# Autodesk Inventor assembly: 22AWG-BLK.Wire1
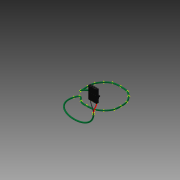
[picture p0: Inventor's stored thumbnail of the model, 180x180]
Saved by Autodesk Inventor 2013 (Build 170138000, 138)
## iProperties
Part Number: 22AWG-BLK.Wire1
Material: Default
Description: 22AWG-BLK
Stock Number: 22AWG-BLK
Density: 1 g/cm^3
Part Number: 22AWG-RED.Wire2
Description: 22AWG-RED
Stock Number: 22AWG-RED
ParentFileIdentifier: 5|1|0|0|180|2|0|0|80|0|65|0|84|0|72|0|83|0|59|0|67|0|58|0|92|0|80|0|114|0|111|0|103|0|114|0|97|0|109|0|32|0|70|0|105|0|108|0|101|0|115|0|92|0|65|0|117|0|116|0|1
Created: 2007-02
Part Number: Processor Fan Harness
Document SubType Name: Assembly
Designer: floress
Mass: 0.263499 g
Surface Area: 8.95077 cm^2
Volume: 0.263499 cm^3
HarnessSettings: <HarnessSettings><Defaults><Segments><Diameter value="0.200 in" fromwires="True"/><Offset value="0.100 in"/><ColorStyle value="Blue"/><RoundUp value=""/><BendRa
CableDummyParamRefKey: Key:16|2|0|0|16|0|0|0|227|0|0|0|0|0|0|0|129|0|0|0|0|0|0|0|Level:1
Author: floress
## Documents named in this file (3)
- Z:\_DATEN\Personal Computer\Aip\Processor Fan Harness.iam
- Z:\_DATEN\Personal Computer\Aip\Processor Fan Harness.ipt
- Z:\_DATEN\Personal Computer\Aip\Fan Connector.ipt
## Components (4 placed, 4 different names)
1. Fan Connector:1
2. Processor Fan Harness
3. HA_VC_102:1
4. HA_VC_105:1
